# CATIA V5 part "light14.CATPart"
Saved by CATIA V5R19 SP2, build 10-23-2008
Part number: light14
Bounding box of the stored display mesh (mm): x -1179.334 to -853.52, y -554.306 to 554.306, z 618.781 to 677.147
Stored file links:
  C:\BEHROOZ\catia learning\tarh haye mashin\hb\light14.CATPart
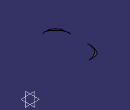
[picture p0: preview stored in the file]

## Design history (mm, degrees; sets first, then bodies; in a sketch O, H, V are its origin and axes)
Body1 (main body)
  Set1
    DatumSurface1
    ThickSurface1: Surface DatumSurface1, TopOffset 1, BotOffset 0
    DatumSurface2
    ThickSurface2: Surface DatumSurface2, TopOffset 1, BotOffset 0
